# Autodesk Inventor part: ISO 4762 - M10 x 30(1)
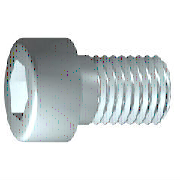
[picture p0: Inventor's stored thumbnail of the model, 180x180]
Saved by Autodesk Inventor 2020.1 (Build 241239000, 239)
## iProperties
Created: 2019-01
Part Number: ISO 4762 - M10 x 30(1)
Material: Edelstahl, 440C
Description: Innensechskantschraube
Document SubType Name: Modeling
Standard: ISO 4762
Designer: lutzd
Standard Revision: Fourth edition 2004-03-01
Standards Organization: ISO
Language: de-DE
Size Designation: M10 x 30
Categories: <MemberInstance><Categories><Category DisplayName="Verbindungselemente" InternalName="e4da775c-781d-43d5-af7c-5136215cf5a6" Mnemonic="FSTN"><Category DisplayNam
Mass: 31.0685 g
Surface Area: 19.595 cm^2
Volume: 4.00884 cm^3
Density: 7.75 g/cm^3
Appearance: Halbpoliert
IsCustomPart: 0
Author: lutzd
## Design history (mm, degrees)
body "Solid1"
sketch "Skizze1"
  geometry: L1 (-2.333, 0)-(30, 0); L2 (30, 0)-(30, 5); L3 (30, 5)-(3.75, 5); L4 (3.75, 5)-(2.83, 5); L5 (2.83, 5)-(0, 5); L6 (0, 5)-(0, 8); L7 (0, 8)-(-10, 8); L8 (-10, 8)-(-10, 4.619); L9 (-10, 4.619)-(-5, 4.619); L10 (-5, 4.619)-(-2.333, 0); L11 (-18, 0)-(38, 0) reference; L12 (0, -1.6)-(0, 9.6) reference; L13 (3.75, 5)-(0, 5)
  constraints: 22 end point, 6 parallel, 2 collinear, 2 perpendicular, 1 horizontal, 1 point on line
  dimensions: "d1" = 26.25 distance from line of L3.end L2 (= GEL); "d2" = 0.92028 distance of L4.end L3.end (computed from GAL); "d3" = 10 distance between parallel lines of L8 L6 (= KOH); "d4" = 5 distance of L8.end L9.end (= INTI); "d5" = 60 deg angle of L10 L1; "d6" = 10 diameter of L3 L1 (= GD); "d7" = 10 diameter of L5 L1 (= BDM); "d8" = 9.2376 diameter of L9 L1 (= 1.1547 x SW); "d9" = 16 diameter of L7 L1 (= KOD); "d26" = 30 distance between parallel lines of L12 L2 (= NLG)
workplane "Work Plane1"
fillet "Fillet2" dims "d30" = 0.1 (= R)
revolve "Körper" stored, may be unused: angle "d10" = 90 deg
sketch "Skizze2"
  geometry: L1 (0, -11.2)-(0, 11.2) reference; L2 (-11.2, 0)-(11.2, 0) reference; L3 (4.619, 0)-(2.309, -4); L4 (2.309, -4)-(-2.309, -4); L5 (-2.309, -4)-(-4.619, 0); L6 (-4.619, 0)-(-2.309, 4); L7 (-2.309, 4)-(2.309, 4); L8 (2.309, 4)-(4.619, 0); 2 further points
  constraints: 12 end point, 1 coincident, 1 horizontal alignment, 1 point on line, 12 other
extrude "Loch" join sketch "Skizze2" stored distance "d11" = 10; taper "d12" = 0 deg
fillet "Rundung1" dims "d17" = 1 (= RR)
feature "Gewinde" dims "d13" = 26.25 (= GEL), "d14" = 0
chamfer "Fase1" distance "d15" = 0.92018 (= -0.5 x SPD + 0.5 x GD); stored, may be unused: second distance "d16" = 0.92018 (= GUL), angle "d27" = 45 deg
other parameters: "GD" = 10 [user parameter; used in 2 equation terms], "NLG" = 30 [user parameter; used in 1 equation term], "GEL" = 26.25 [user parameter; used in 2 equation terms], "KOD" = 16 [user parameter; used in 1 equation term], "KOH" = 10 [user parameter; used in 1 equation term], "INTI" = 5 [user parameter; used in 1 equation term], "GAL" = 0.92018 (= 0.61345 x PTC) [user parameter; used in 1 equation term], "GUL" = 0.92018 (= 0.61345 x PTC) [user parameter; used in 1 equation term], "BDM" = 10 (= NND) [user parameter; used in 1 equation term], "SW" = 8 [user parameter; used in 2 equation terms], "RR" = 1 [user parameter; used in 1 equation term], "SPD" = 8.15965 (= NND - 1.2269 x PTC) [user parameter; used in 1 equation term], "d19" = 0, "d28" = 0, "d29" = 0, "R" = 0.1 [user parameter; used in 1 equation term], "TOA" = 30 deg [user parameter], "GD1" = 8.15965 (= THREADDIA - 1.2269 x PTC) [user parameter], "FAWI" = 45 deg [user parameter], "TPU" = 6.66667 (computed from PTC) [user parameter], "PTC" = 1.5 [user parameter; used in 5 equation terms], "E0" = 9.24 (= 1.155 x SW) [user parameter]
